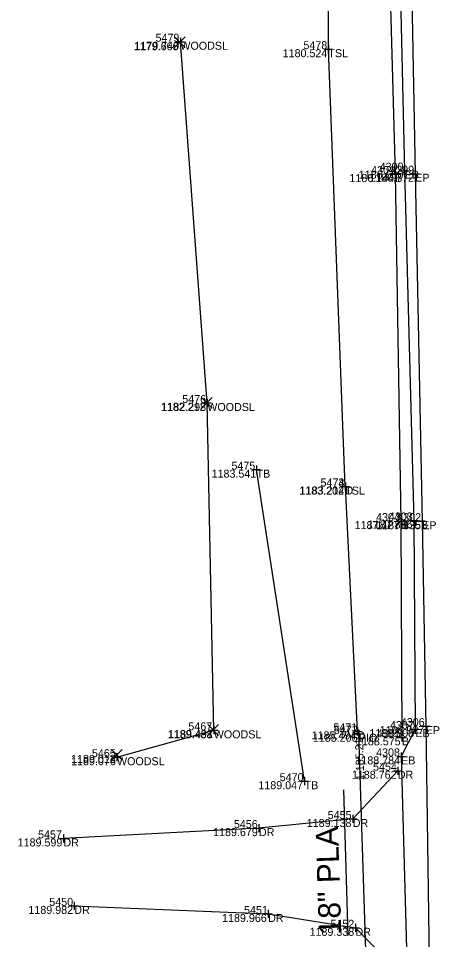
# Model space of a CAD drawing. Extents: x 2044996 to 2050343, y 455232 to 458054.
# Drawn here: x 2047551.9 to 2047604.4, y 457864.6 to 457979.7 of the extents above; entities that cross this region are included whole.
import ezdxf

# ---------------------------------------------------------------- set-up
doc = ezdxf.new("R2010")
doc.units = 0
for name, color, linetype in [('DR_X_Ditch', 7, 'Continuous'), ('DR_X_Elev_Flow', 7, 'Continuous'), ('DR_X_Storm_Sewer', 7, 'Continuous'), ('DR_X_Text', 7, 'Continuous'), ('DT_X_Contour_Minor', 7, 'Continuous'), ('DT_X_Contour_Text', 7, 'Continuous'), ('DT_X_Spot_Elev', 7, 'Continuous'), ('DT_X_Triangles', 7, 'Continuous'), ('DT_X_Void', 7, 'Continuous'), ('PV_X_Driveway', 7, 'Continuous'), ('PV_X_EOP', 7, 'Continuous'), ('PV_X_Shoulder_Aggregate', 7, 'Continuous'), ('SC_Scratch1', 7, 'Continuous'), ('SV_X_Break_Lines', 7, 'Continuous'), ('SV_X_Toe_of_Slope', 7, 'Continuous'), ('SV_X_Top_of_Bank', 7, 'Continuous'), ('VG_X_Tree_Line_Lt', 7, 'Continuous')]:
    doc.layers.add(name, color=color, linetype=linetype)

msp = doc.modelspace()

# ---------------------------------------------------------------- linework, layer by layer
at = {"layer": 'DR_X_Ditch'}
msp.add_lwpolyline([(2047594.17, 457890.6), (2047592.68, 457921.2)], dxfattribs=at)
at = {"layer": 'DR_X_Elev_Flow'}
for p, q in [((2047593.85, 457890.3), (2047594.85, 457890.3)), ((2047594.35, 457890.8), (2047594.35, 457889.8)), ((2047594.35, 457890.3), (2047594.35, 457890.3))]:
    msp.add_line(p, q, dxfattribs=at)
at = {"layer": 'DR_X_Storm_Sewer'}
msp.add_line((2047595.49, 457854.21), (2047594.35, 457890.3), dxfattribs=at)
at = {"layer": 'DR_X_Text'}
msp.add_line((2047592.42, 457883.29), (2047592.99, 457865.08), dxfattribs=at)
at = {"layer": 'DT_X_Spot_Elev'}
for p, q in [((2047571.33, 457976.04), (2047572.66, 457977.37)), ((2047571.33, 457977.37), (2047572.66, 457976.04)), ((2047574.71, 457930.99), (2047576.04, 457932.33)), ((2047574.71, 457932.33), (2047576.04, 457930.99)), ((2047575.5, 457890.1), (2047576.83, 457891.44)), ((2047575.5, 457891.44), (2047576.83, 457890.1)), ((2047563.48, 457887), (2047564.82, 457888.33)), ((2047563.48, 457888.33), (2047564.82, 457887))]:
    msp.add_line(p, q, dxfattribs=at)
at = {"layer": 'DT_X_Void'}
for p, q in [((2047571.57, 457976.77), (2047572.57, 457976.77)), ((2047572.07, 457977.27), (2047572.07, 457976.27)), ((2047572.07, 457976.77), (2047572.07, 457976.77)), ((2047590.55, 457976.34), (2047590.55, 457975.34)), ((2047590.05, 457975.84), (2047591.05, 457975.84)), ((2047590.55, 457975.84), (2047590.55, 457975.84)), ((2047598.39, 457960.24), (2047599.39, 457960.24)), ((2047598.89, 457960.74), (2047598.89, 457959.74)), ((2047598.89, 457960.24), (2047598.89, 457960.24)), ((2047599.57, 457960.66), (2047600.57, 457960.66)), ((2047600.07, 457961.16), (2047600.07, 457960.16)), ((2047600.07, 457960.66), (2047600.07, 457960.66)), ((2047600.88, 457960.28), (2047601.88, 457960.28)), ((2047601.38, 457960.78), (2047601.38, 457959.78)), ((2047601.38, 457960.28), (2047601.38, 457960.28)), ((2047574.93, 457931.63), (2047575.93, 457931.63)), ((2047575.43, 457932.13), (2047575.43, 457931.13)), ((2047575.43, 457931.63), (2047575.43, 457931.63)), ((2047581.58, 457923.8), (2047581.58, 457922.8)), ((2047581.08, 457923.3), (2047582.08, 457923.3)), ((2047581.58, 457923.3), (2047581.58, 457923.3)), ((2047592.15, 457921.18), (2047593.15, 457921.18)), ((2047592.18, 457921.2), (2047593.18, 457921.2)), ((2047592.65, 457921.68), (2047592.65, 457920.68)), ((2047592.65, 457921.18), (2047592.65, 457921.18)), ((2047592.68, 457921.7), (2047592.68, 457920.7)), ((2047592.68, 457921.2), (2047592.68, 457921.2)), ((2047599.09, 457916.87), (2047600.09, 457916.87)), ((2047599.59, 457917.37), (2047599.59, 457916.37)), ((2047599.59, 457916.87), (2047599.59, 457916.87)), ((2047600.71, 457916.95), (2047601.71, 457916.95)), ((2047601.21, 457917.45), (2047601.21, 457916.45)), ((2047601.21, 457916.95), (2047601.21, 457916.95)), ((2047601.76, 457916.86), (2047602.76, 457916.86)), ((2047602.26, 457917.36), (2047602.26, 457916.36)), ((2047602.26, 457916.86), (2047602.26, 457916.86)), ((2047576.24, 457891.23), (2047576.24, 457890.23)), ((2047601.4, 457891.38), (2047601.4, 457890.38)), ((2047602.21, 457891.25), (2047603.21, 457891.25)), ((2047602.71, 457891.75), (2047602.71, 457890.75)), ((2047602.71, 457891.25), (2047602.71, 457891.25)), ((2047575.74, 457890.73), (2047576.74, 457890.73)), ((2047576.24, 457890.73), (2047576.24, 457890.73)), ((2047593.67, 457890.6), (2047594.67, 457890.6)), ((2047594.17, 457891.1), (2047594.17, 457890.1)), ((2047594.17, 457890.6), (2047594.17, 457890.6)), ((2047599.73, 457890.35), (2047599.73, 457889.35)), ((2047600.9, 457890.88), (2047601.9, 457890.88)), ((2047601.4, 457890.88), (2047601.4, 457890.88)), ((2047599.23, 457889.85), (2047600.23, 457889.85)), ((2047599.73, 457889.85), (2047599.73, 457889.85)), ((2047564.16, 457887.87), (2047564.16, 457886.87)), ((2047599.63, 457887.97), (2047599.63, 457886.97)), ((2047563.66, 457887.37), (2047564.66, 457887.37)), ((2047564.16, 457887.37), (2047564.16, 457887.37)), ((2047599.13, 457887.47), (2047600.13, 457887.47)), ((2047599.63, 457887.47), (2047599.63, 457887.47)), ((2047598.71, 457885.68), (2047599.71, 457885.68)), ((2047599.21, 457886.18), (2047599.21, 457885.18)), ((2047599.21, 457885.68), (2047599.21, 457885.68)), ((2047587.08, 457884.37), (2047588.08, 457884.37)), ((2047587.58, 457884.87), (2047587.58, 457883.87)), ((2047587.58, 457884.37), (2047587.58, 457884.37)), ((2047593.09, 457879.65), (2047594.09, 457879.65)), ((2047593.59, 457880.15), (2047593.59, 457879.15)), ((2047593.59, 457879.65), (2047593.59, 457879.65)), ((2047581.38, 457878.51), (2047582.38, 457878.51)), ((2047581.88, 457879.01), (2047581.88, 457878.01)), ((2047581.88, 457878.51), (2047581.88, 457878.51)), ((2047557.47, 457877.72), (2047557.47, 457876.72)), ((2047556.97, 457877.22), (2047557.97, 457877.22)), ((2047557.47, 457877.22), (2047557.47, 457877.22)), ((2047558.83, 457869.29), (2047558.83, 457868.29)), ((2047558.33, 457868.79), (2047559.33, 457868.79)), ((2047558.83, 457868.79), (2047558.83, 457868.79)), ((2047583.02, 457868.28), (2047583.02, 457867.28)), ((2047582.52, 457867.78), (2047583.52, 457867.78)), ((2047583.02, 457867.78), (2047583.02, 457867.78)), ((2047593.43, 457866.05), (2047594.43, 457866.05)), ((2047593.93, 457866.55), (2047593.93, 457865.55)), ((2047593.93, 457866.05), (2047593.93, 457866.05))]:
    msp.add_line(p, q, dxfattribs=at)
at = {"layer": 'PV_X_Driveway'}
for points in [[(2047599.21, 457885.68), (2047593.59, 457879.65), (2047581.88, 457878.51), (2047557.47, 457877.22)], [(2047558.83, 457868.79), (2047583.02, 457867.78), (2047593.93, 457866.05), (2047599.71, 457860.14)]]:
    msp.add_lwpolyline(points, dxfattribs=at)
at = {"layer": 'PV_X_EOP'}
for p, q in [((2047600.54, 458005.56), (2047601.38, 457960.28)), ((2047601.38, 457960.28), (2047602.26, 457916.86)), ((2047602.26, 457916.86), (2047602.71, 457891.25)), ((2047602.71, 457891.25), (2047603.22, 457854.47))]:
    msp.add_line(p, q, dxfattribs=at)
at = {"layer": 'PV_X_Shoulder_Aggregate'}
for p, q in [((2047598.97, 458005.63), (2047600.07, 457960.66)), ((2047600.07, 457960.66), (2047601.21, 457916.95)), ((2047601.21, 457916.95), (2047601.4, 457890.88)), ((2047601.4, 457890.88), (2047599.63, 457887.47)), ((2047599.63, 457887.47), (2047600.45, 457857.64))]:
    msp.add_line(p, q, dxfattribs=at)
at = {"layer": 'SV_X_Break_Lines'}
msp.add_lwpolyline([(2047596.77, 458052.99), (2047597.63, 458005.14), (2047598.89, 457960.24), (2047599.59, 457916.87), (2047599.73, 457889.85)], dxfattribs=at)
at = {"layer": 'SV_X_Toe_of_Slope'}
msp.add_lwpolyline([(2047592.65, 457921.18), (2047590.55, 457975.84), (2047590.57, 458028.62)], dxfattribs=at)
at = {"layer": 'SV_X_Top_of_Bank'}
msp.add_lwpolyline([(2047587.58, 457884.37), (2047581.58, 457923.3)], dxfattribs=at)
at = {"layer": 'VG_X_Tree_Line_Lt'}
msp.add_lwpolyline([(2047564.16, 457887.37), (2047576.24, 457890.73), (2047575.43, 457931.63), (2047572.07, 457976.77)], dxfattribs=at)

# ---------------------------------------------------------------- texts
at = {"layer": 'DR_X_Text'}
msp.add_text('18" PLA', height=2.8, rotation=91.7999, dxfattribs=at).set_placement((2047592.17, 457865.15))
at = {"layer": 'DT_X_Contour_Minor'}
for s, p in [('1179.666', (2047566.26, 457975.7)), ('1179.740', (2047566.34, 457975.77)), ('1180.524', (2047584.84, 457974.84)), ('1186.144', (2047593.18, 457959.24)), ('1186.600', (2047594.34, 457959.66)), ('1186.772', (2047595.65, 457959.28)), ('1182.212', (2047569.64, 457930.66)), ('1182.298', (2047569.7, 457930.63)), ('1183.541', (2047575.97, 457922.3)), ('1183.202', (2047586.92, 457920.18)), ('1183.214', (2047586.98, 457920.2)), ('1187.427', (2047593.82, 457915.87)), ('1187.886', (2047595.47, 457915.95)), ('1187.835', (2047596.52, 457915.86)), ('1188.927', (2047596.94, 457890.25)), ('1189.488', (2047570.5, 457889.73)), ('1189.491', (2047570.55, 457889.77)), ('1185.494', (2047588.46, 457889.6)), ('1185.206', (2047588.61, 457889.3)), ('1188.808', (2047595.67, 457889.88)), ('1188.575', (2047593.99, 457888.85)), ('1189.013', (2047558.43, 457886.66)), ('1189.076', (2047558.43, 457886.37)), ('1188.784', (2047593.92, 457886.47)), ('1188.762', (2047593.48, 457884.68)), ('1189.047', (2047581.81, 457883.37)), ('1189.138', (2047587.85, 457878.65)), ('1189.679', (2047576.16, 457877.51)), ('1189.599', (2047551.76, 457876.22)), ('1189.982', (2047553.1, 457867.79)), ('1189.966', (2047577.28, 457866.78)), ('1189.338', (2047588.2, 457865.05))]:
    msp.add_text(s, height=1, dxfattribs=at).set_placement(p)
at = {"layer": 'DT_X_Contour_Text'}
for s, p in [('WOODSL', (2047572.07, 457975.77)), ('TSL', (2047590.55, 457974.84)), ('B', (2047598.89, 457959.24)), ('EB', (2047600.07, 457959.66)), ('EP', (2047601.38, 457959.28)), ('WOODSL', (2047575.43, 457930.63)), ('TB', (2047581.58, 457922.3)), ('TSL', (2047592.65, 457920.18)), ('D', (2047592.68, 457920.2)), ('B', (2047599.59, 457915.87)), ('EB', (2047601.21, 457915.95)), ('EP', (2047602.26, 457915.86)), ('EP', (2047602.71, 457890.25)), ('WOODSL', (2047576.24, 457889.73)), ('D', (2047594.17, 457889.6)), ('PIO', (2047594.35, 457889.3)), ('EB', (2047601.4, 457889.88)), ('B', (2047599.73, 457888.85)), ('WOODSL', (2047564.16, 457886.37)), ('EB', (2047599.63, 457886.47)), ('DR', (2047599.21, 457884.68)), ('TB', (2047587.58, 457883.37)), ('DR', (2047593.59, 457878.65)), ('DR', (2047581.88, 457877.51)), ('DR', (2047557.47, 457876.22)), ('DR', (2047558.83, 457867.79)), ('DR', (2047583.02, 457866.78)), ('DR', (2047593.93, 457865.05))]:
    msp.add_text(s, height=1, dxfattribs=at).set_placement(p)
at = {"layer": 'DT_X_Triangles'}
for s, p in [('5479', (2047568.97, 457976.77)), ('5478', (2047587.43, 457975.84)), ('4300', (2047596.95, 457960.66)), ('4301', (2047595.89, 457960.24)), ('4299', (2047598.28, 457960.28)), ('5476', (2047572.31, 457931.63)), ('5475', (2047578.45, 457923.3)), ('5473', (2047589.57, 457921.2)), ('5474', (2047589.56, 457921.18)), ('4304', (2047596.5, 457916.87)), ('4303', (2047598.1, 457916.95)), ('4302', (2047599.15, 457916.86)), ('5467', (2047573.07, 457890.73)), ('5471', (2047591.17, 457890.6)), ('5472', (2047591.24, 457890.3)), ('4307', (2047598.24, 457890.88)), ('4306', (2047599.59, 457891.25)), ('4305', (2047596.6, 457889.85)), ('5465', (2047561.03, 457887.37)), ('4308', (2047596.51, 457887.47)), ('5454', (2047596.12, 457885.68)), ('5470', (2047584.47, 457884.37)), ('5455', (2047590.46, 457879.65)), ('5456', (2047578.75, 457878.51)), ('5457', (2047554.31, 457877.22)), ('5450', (2047555.71, 457868.79)), ('5451', (2047580.02, 457867.78)), ('5452', (2047590.81, 457866.05))]:
    msp.add_text(s, height=1, dxfattribs=at).set_placement(p)
at = {"layer": 'SC_Scratch1'}
msp.add_text("1,185.21'", height=1, rotation=91.7999, dxfattribs=at).set_placement((2047595.03, 457884.52))

doc.saveas('drawing.dxf')
